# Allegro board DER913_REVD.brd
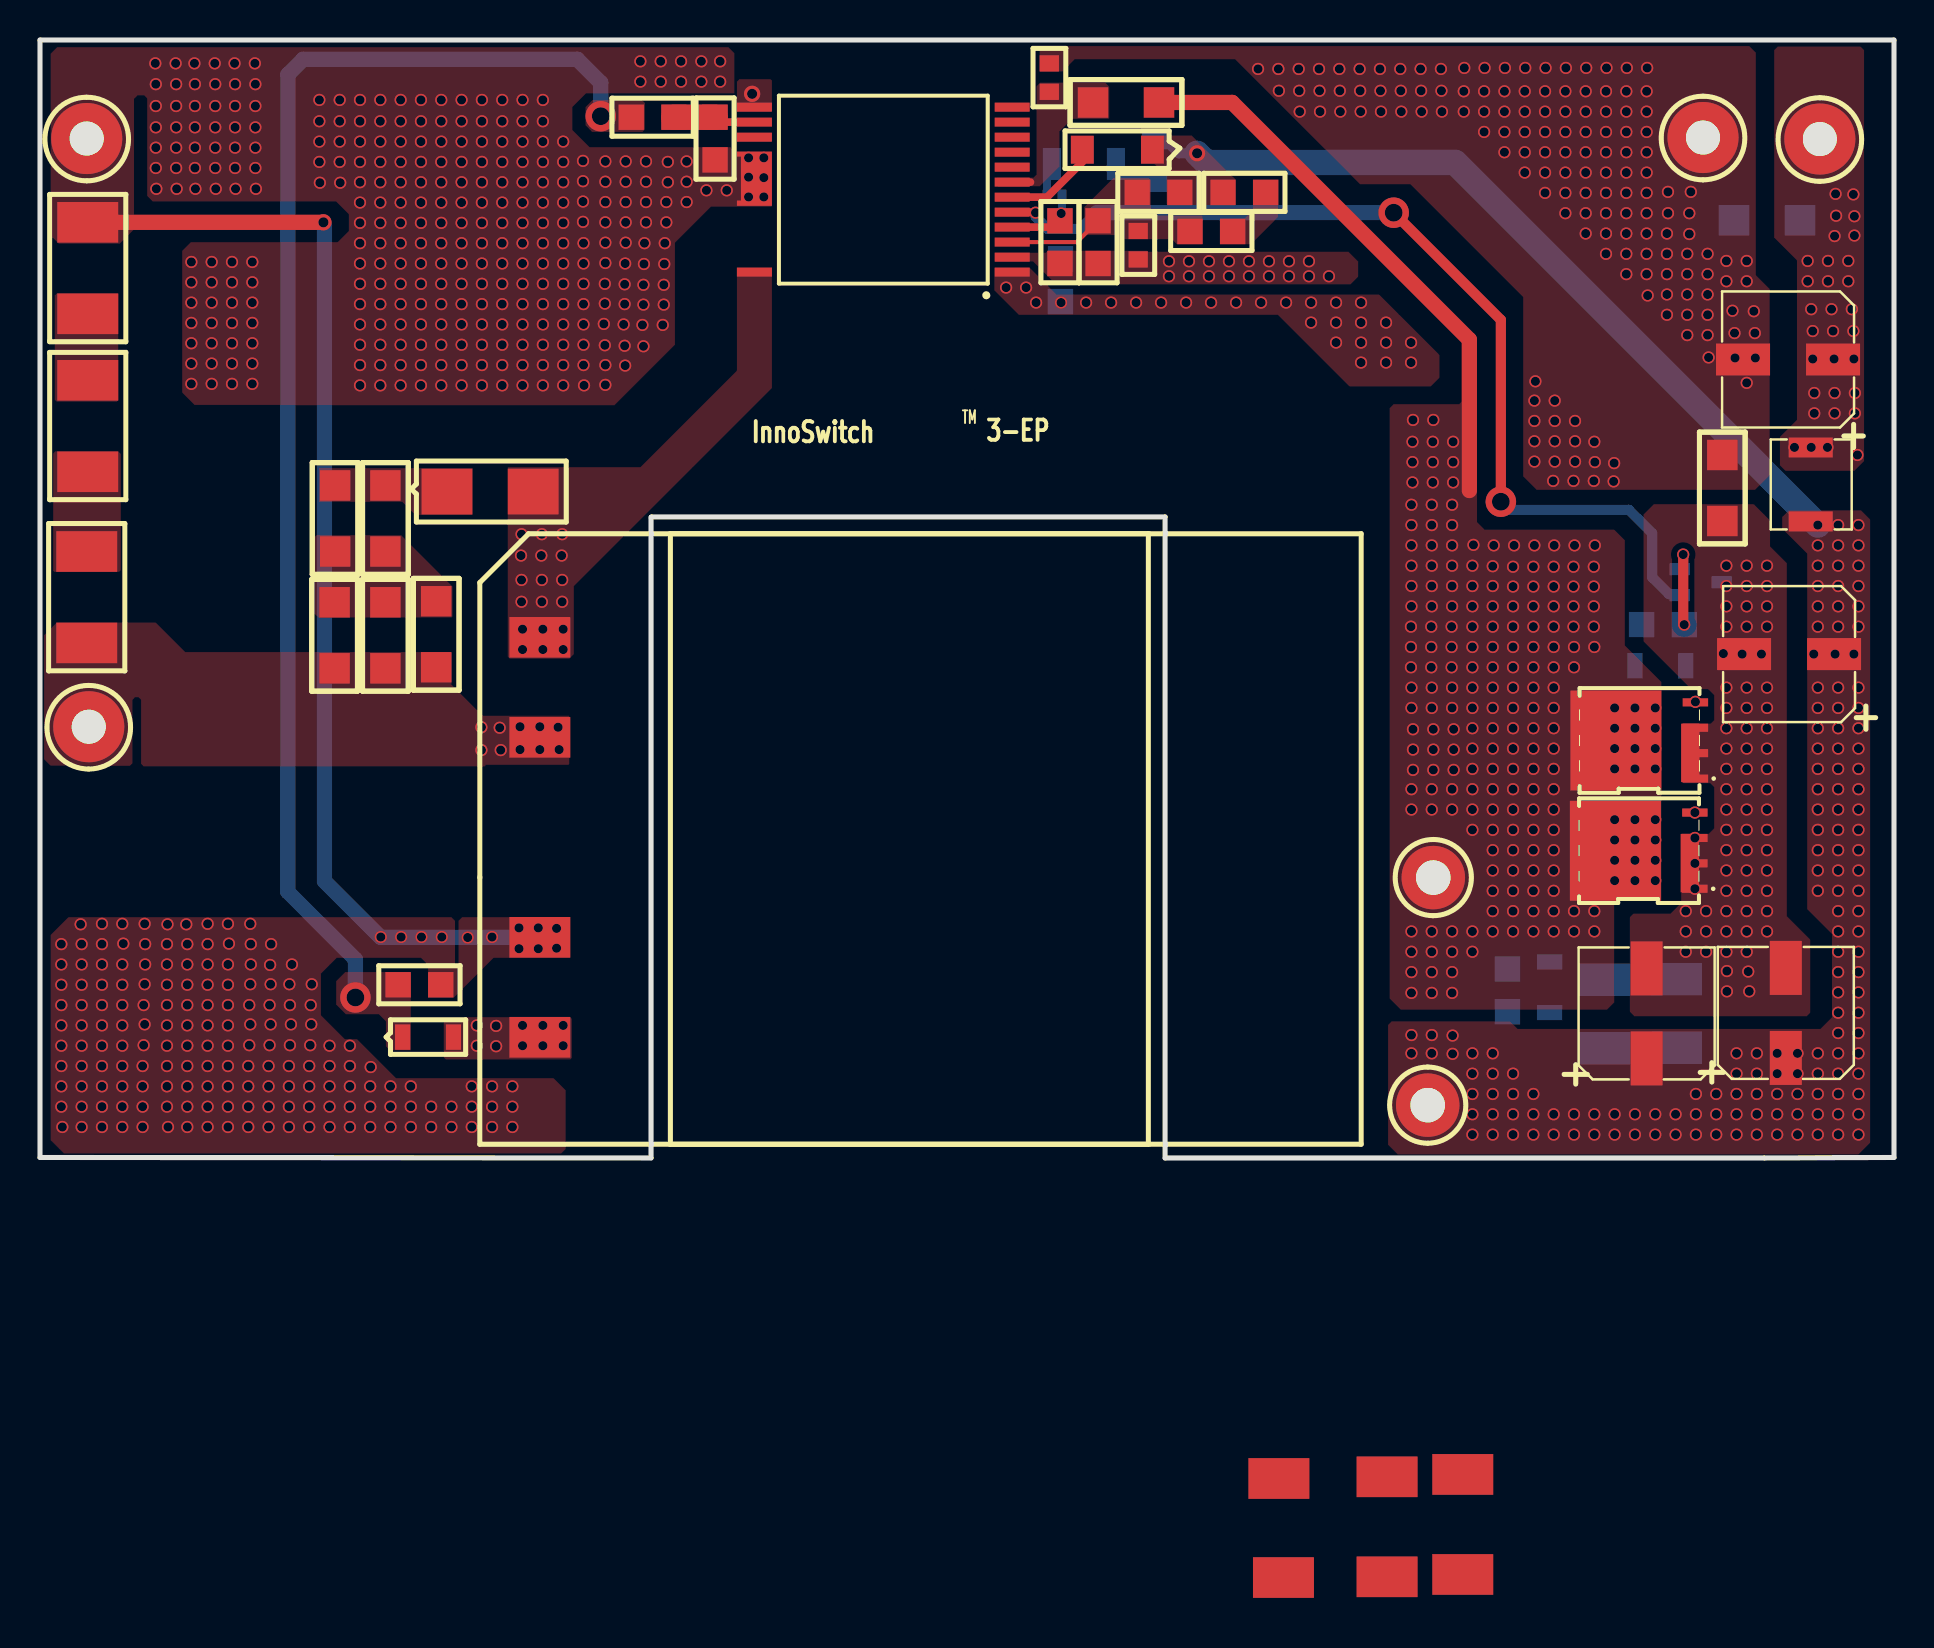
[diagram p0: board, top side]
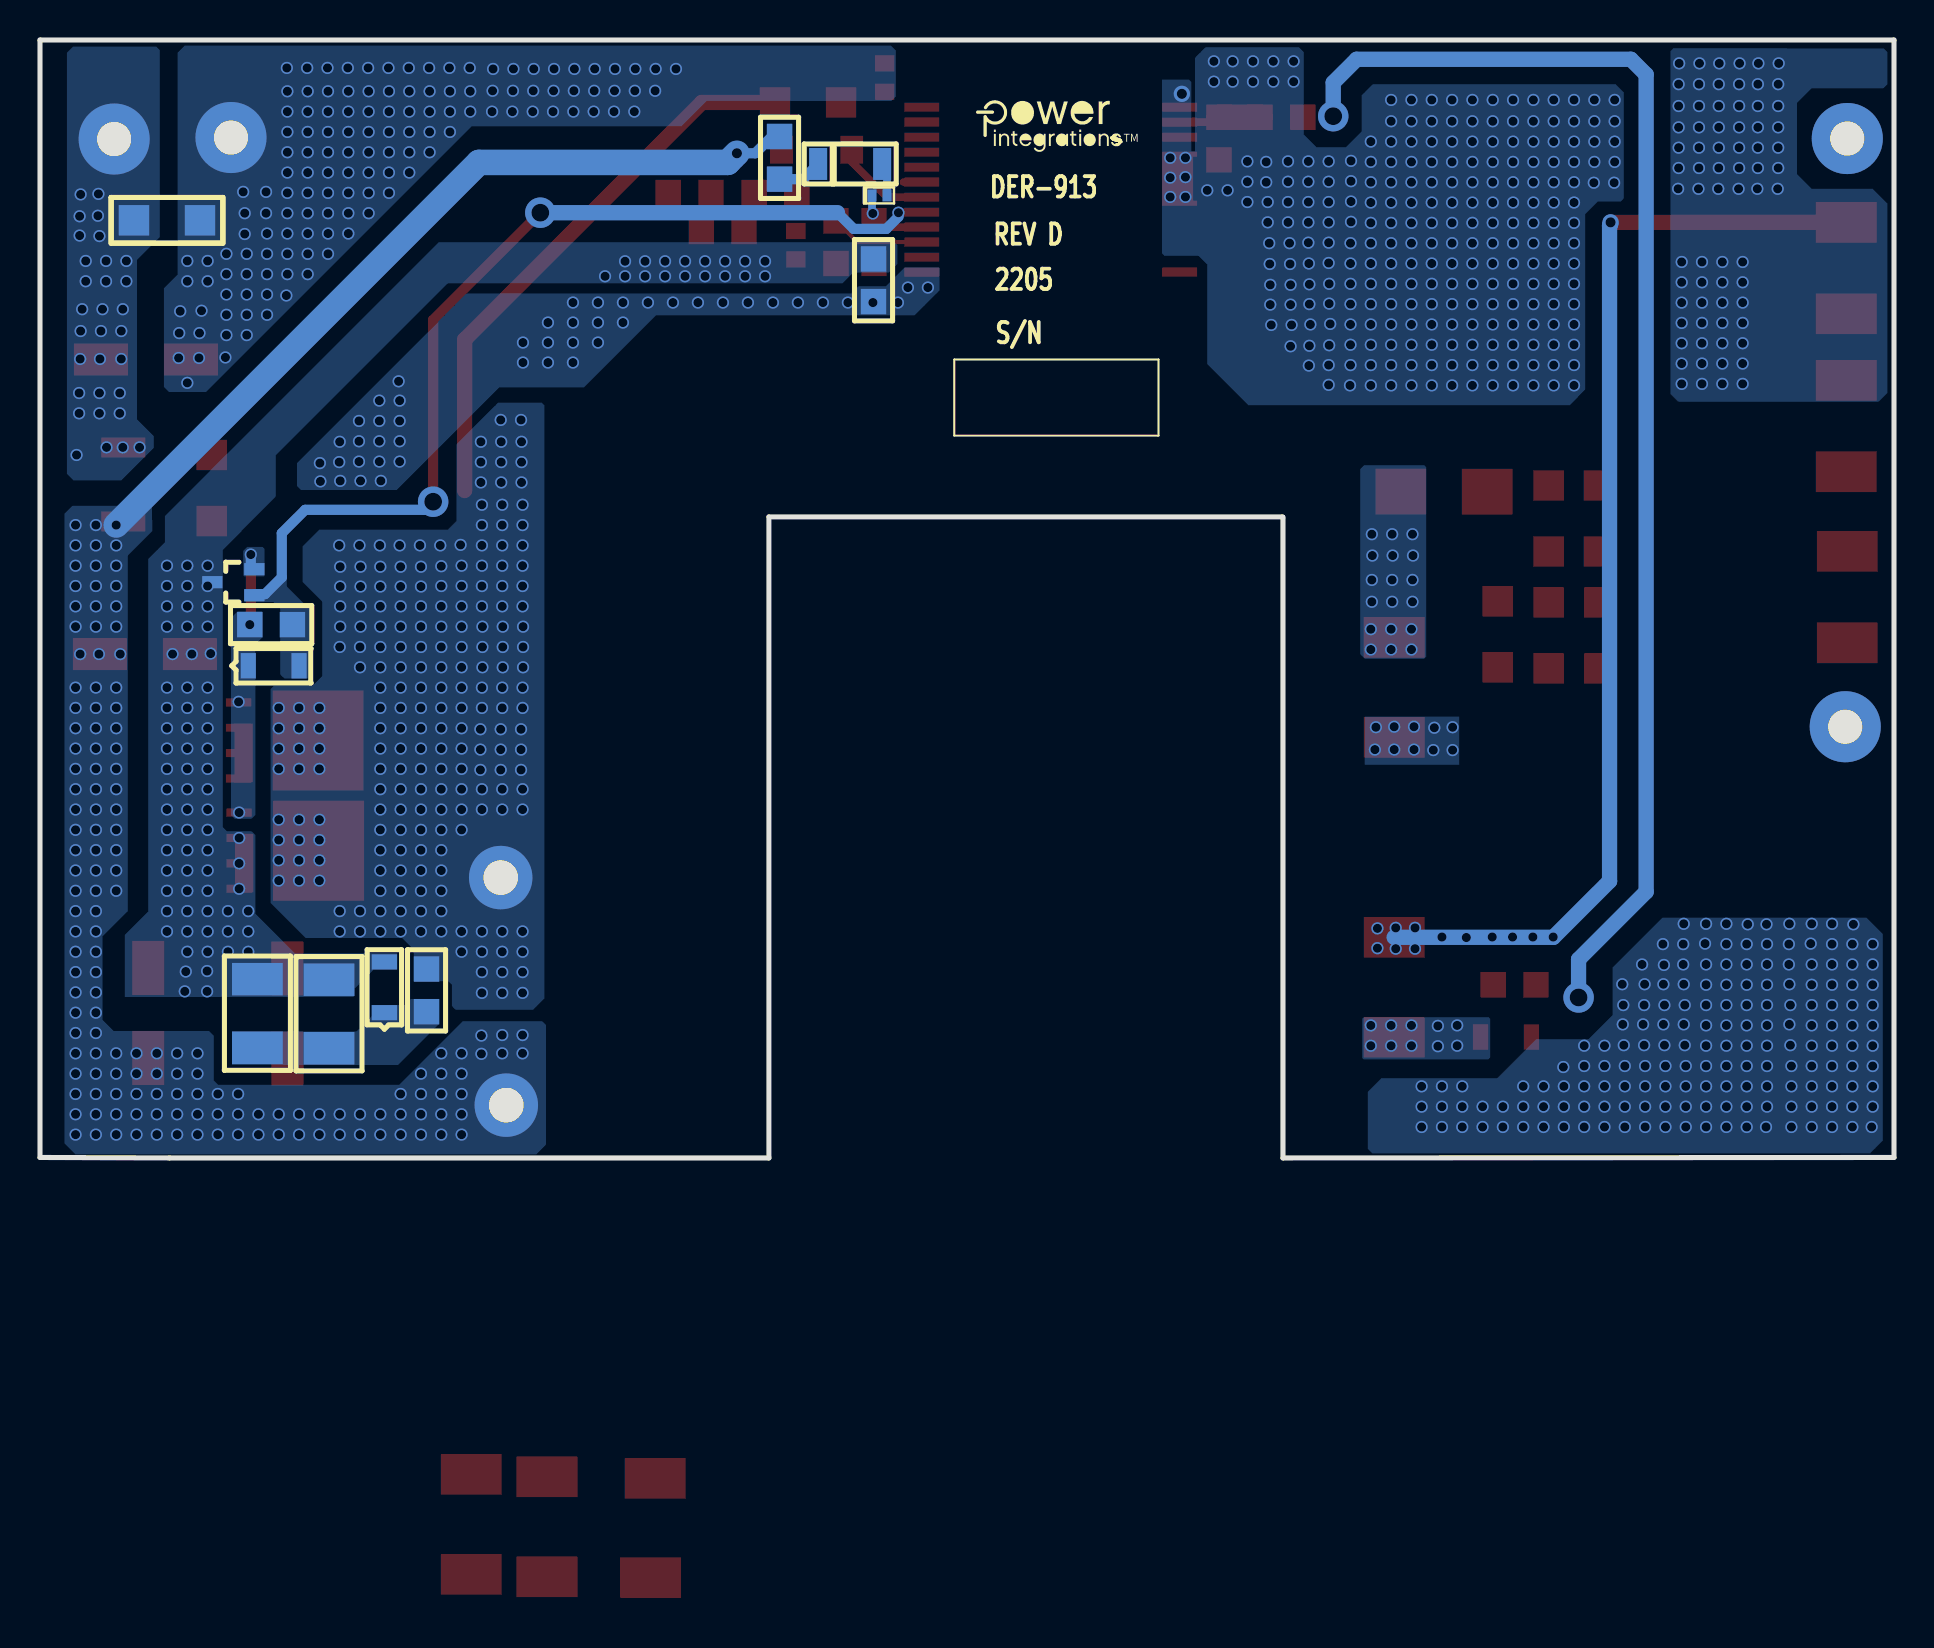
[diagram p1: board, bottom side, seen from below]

Outline 92.71 x 55.91 mm; copper layers: TOP, INNER1, INNER2, BOTTOM. Coordinates in mm from the lower left corner of the outline.
Outline path: 0,55.91 92.71,55.91 92.71,0.03 86.23,0 56.26,0 56.26,32.05 30.58,32.05 30.56,32.03 30.56,0 0,0.03 0,55.91

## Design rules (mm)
constraint set DEFAULT: min track width 0.508

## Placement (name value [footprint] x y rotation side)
C1A  47 nF  [PISMC1812]  2.34 25.76 90 top
C1B  47 nF  [PISMC1812]  2.39 34.32 90 top
C1C  47 nF  [PISMC1812]  2.39 42.21 90 top
C2  1 nF  [PISMC1206]  19.81 24.54 90 top
C3  22 uF  [PISMC0805]  17.91 8.66 0 top
C4  0.47 uF  [PISMC0805]  33.76 52.04 270 top
C5  2.2 nF  [PISMC0805]  73.38 9.45 270 bottom
C6  2.2 uF  [PISMC0805]  51 44.73 90 top
C7  330 pF  [PISMC0603]  54.91 44.93 90 top
C8  10 nF  [PISMC0805]  59.64 46.33 180 top
C9  120 uF  [PISMCUCC_F80ALELECT]  80.34 4.98 90 top
C10  120 uF  [PISMCUCC_F80ALELECT]  87.3 5 90 top
C11  120 uF  [PISMCUCC_F80ALELECT]  89.71 25.2 180 top
C13  120 uF  [PISMCUCC_F80ALELECT]  89.66 39.93 180 top
C14  2.2 uF  [PISMC1206]  88.01 46.89 180 bottom
C16  330 pF  [PISMC0603]  50.47 53.31 90 top
C17  10 nF  [PISMC0805]  51.03 44.96 270 bottom
D1  ACGRAS1W-HF  [PISMDO214AC12]  20.35 33.32 0 top
D2  NSVBAS21AHT1G  [PISMSOD323]  18.14 6.05 0 top
D3  SD103CWS-E3-08  [PISMSOD323]  79.76 24.61 0 bottom
D4  NSVBAS21AHT1G  [PISMSOD323]  75.49 7.26 90 bottom
D5  SBR0240LPW-7B  [PI_SM_DFN1006-2]  51.1 48.13 180 bottom
FL1  Hole_70mils  [PI_HOLE_70MIL]  69.39 2.62 0 top
FL2  Hole_70mils  [PI_HOLE_70MIL]  69.67 14 0 top
L1  SRP4020TA-1R5M  [PI_SM_2-SMD]  88.54 33.68 90 top
NOREF  -  []  -230.38 -144.4 0 top
NOREF#2  -  []  0 55.91 0 top
NOREF#3  -  []  -152.56 54.62 0 top
NOREF#4  -  []  92.71 0.03 90 top
NOREF#5  -  []  46.46 52.78 180 bottom
Q1  SQJ454EP-T1_GE3  [PISMPQFN5X6BLA]  82.78 18.97 90 top
Q2  SQJ454EP-T1_GE3  [PISMPQFN5X6BLA]  82.75 13.46 90 top
Q3  DMG1013UWQ-7  [PISMSOT323_GSD]  81.99 28.14 90 bottom
R1  1 Meg  [PISMR1206]  17.27 24.49 90 top
R2  1 Meg  [PISMR1206]  14.73 24.49 90 top
R3  82  [PISMR1206]  14.76 30.33 90 top
R4  82  [PISMR1206]  17.27 30.33 90 top
R5  7.68 k  [PISMR0805]  29.57 52.04 0 top
R6  100  [PISMR1206]  55.96 52.78 180 top
R7  20  [PISMR1210]  78.26 5.49 90 bottom
R8  20  [PISMR1210]  81.84 5.51 90 bottom
R9  5.49 k  [PISMR0805]  52.91 46.86 270 top
R10  100 k  [PISMR0805]  57 48.29 180 top
R11  15 k  [PISMR0805]  59.16 48.29 0 top
R12  0.015  [PISMR1206]  84.12 31.85 90 top
R13  4.7  [PISMR0805]  82.22 26.67 180 bottom
R14  4.7  [PISMR0805]  55.73 51.08 270 bottom
RTN  BLK  [PITPKEYSTONE125X125]  83.16 51.03 0 top
T1  EIQ30  [PIBOBBINEQI3010PSMTSLIMCORE]  24.99 26.04 90 top
U1  INN3647C  [PI_IC_INSOP_24D]  48.62 44.3 180 top
VIN+  RED  [PITPKEYSTONE125X125]  2.44 21.56 0 top
VIN-  BLK  [PITPKEYSTONE125X125]  2.34 50.98 0 top
VO  RED  [PITPKEYSTONE125X125]  89 50.95 0 top
VR1  SZMMSZ4683T1G  [PI_SM_SOD-123_12]  55.63 50.42 180 top
VR2  TZMB22-GS08  [PI_SM_SOD80C]  53.8 49.71 180 bottom

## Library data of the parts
C1A C1B C1C C2-C6 C8 C14 C16 C17 = CAP NP
C7 = CAP NP: alternate symbols: (pismc0603_1)
C9-C11 C13 = CAP POL
D1 D5 = DIODE
D2 D4 = DIODE: alternate symbols: (pismsod323_1)
D3 = DIODE SCHOTTKY: alternate symbols: (pismsod323_1)
FL1 FL2 = FlyingLead
L1 = INDUCTOR
Q1 Q2 = FET_N_SGD_123_4_5678: alternate symbols: (pismpqfn5x6bl)
Q3 = FET_P_GSD
R1-R14 = R
RTN VIN+ VIN- VO = TESTPOINT
T1 = BEQI30_10P_SMT/GENERIC_7
U1 = Inno3AQ_P15_3
VR1 VR2 = DIODE_ZENER

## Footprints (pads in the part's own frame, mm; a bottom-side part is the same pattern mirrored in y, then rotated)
PI_HOLE_70MIL
  round 3.175 hole 1.727: 1(0,0.025)
PI_IC_INSOP_24D
  rect 1.75x0.45 smd: 1(0,0) 2(0,-0.749) 3(0,-1.501) 4(0,-2.25) 5(0,-3) 6(0,-3.749) 7(0,-4.501) 8(0,-5.25) 9(0,-6) 10(0,-6.749) 11(0,-7.501) 12(0,-8.25) 13(12.89,-8.25) 14(12.89,-7.501) 15(12.89,-6.749) 24(12.89,0)
  custom 0.437x0.437 smd: 16(12.89,-4.671)
PI_SM_2-SMD
  rect 1.001x2.2 smd: 1(-1.849,0) 2(1.849,0)
PI_SM_DFN1006-2
  rect 0.45x0.6 smd: 1(0,0) 2(0.75,0)
PI_SM_SOD80C
  rect 0.9x1.6 smd: 1(0,0) 2(3.2,0)
PI_SM_SOD-123_12
  rect 1.143x1.397 smd: 1(0,0) 2(3.505,0)
PIBOBBINEQI3010PSMTSLIMCORE
  rect 2.032x3.048 smd: 1(0,0) 2(-5.001,0) 3(-42.062,-36.957) 4(-15.001,0) 5(-20,0) 6(-47.015,-37.186) 7(-46.98,-42.367) 8(-41.979,-42.367) 9(-46.86,-46.152) 10(-41.859,-46.152)
PISMC0603
  rect 0.813x0.965 smd: 1(0,0) 2(1.422,0)
PISMC0805
  rect 1.27x1.27 smd: 1(0,0) 2(2.134,0)
PISMC1206
  rect 1.524x1.524 smd: 1(0,0) 2(3.302,0)
PISMC1812
  rect 2.032x3.048 smd: 1(0,0) 2(4.572,0)
PISMCUCC_F80ALELECT
  rect 2.7x1.6 smd: 1(0,0) 2(4.501,0)
PISMDO214AC12
  rect 2.54x2.286 smd: 1(0,0) 2(4.318,0)
PISMPQFN5X6BLA
  rect 0.406x1.27 smd: 1(0,0) 2(1.27,0) 3(2.54,0) 4(3.81,0)
  rect 0.406x1.219 smd: 5(3.81,5.588) 6(2.54,5.588) 7(1.27,5.588) 8(0,5.588)
PISMR0805
  rect 1.27x1.27 smd: 1(0,0) 2(2.134,0)
PISMR1206
  rect 1.524x1.524 smd: 1(0,0) 2(3.302,0)
PISMR1210
  rect 1.626x2.54 smd: 1(0,0) 2(3.429,0)
PISMSOD323
  rect 0.762x1.27 smd: 1(0,0) 2(2.54,0)
PISMSOT323_GSD
  rect 0.61x1.016 smd: 1(0,0) 2(0.65,2.101) 3(1.301,0)
PITPKEYSTONE125X125
  round 3.556 hole 1.702: 1(0,0)

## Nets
GND: C1C.2 C3.2 C4.2 T1.4 U1.13(VPIN) U1.16 VIN-.1
GND SIGNAL: C13.2 C14.2 C16.2 C17.2 R12.2 RTN.1 U1.1
NC8: U1.8
NC9: U1.9
NC10: U1.10
NC11: U1.11
NC12: U1.12
NC15: U1.15
VO: C9.1 C10.1 C11.1 FL1.1 L1.1 R10.1 R11.1 R14.1 VR1.1
N37213: C1A.1 C2.1 R1.1 R2.1 T1.2 VIN+.1
N37461: C5.2 D4.1 R7.1 R8.1
N37469: C6.1 C7.1 C9.2 C10.2 C11.2 C17.1 D4.2 Q1.1 Q1.2 Q1.3(S3) Q2.1 Q2.2 Q2.3(S3) Q3.2(S) R7.2 R8.2 R9.2 R12.1 U1.2
N37817: C1A.2 C1B.1
N38055: C3.1 D2.1 R5.1
N38189: C4.1 R5.2 U1.14
N51802: C13.1 C14.1 L1.2 VO.1
N100534: C2.2 R1.2 R2.2 R3.1 R4.1
N100538: D1.1 R3.2 R4.2
N104424: C5.1 FL2.1 Q1.5 Q1.6 Q1.7 Q1.8 Q2.5 Q2.6 Q2.7 Q2.8 R6.1
N108749: C7.2 C8.2 R9.1 R10.2 U1.3
N109628: U1.6 VR1.2
N109833: C8.1 R11.2
N12285951: D3.2(CATHODE) Q1.4 Q2.4 Q3.3 R13.1
N12285992: D3.1 Q3.1 R13.2 U1.5
N12290249: D2.2 T1.5
N12293127: C16.1 R6.2 U1.7
N12298344: D1.2 T1.1 U1.24
N12325575: C6.2 D5.1 U1.4
N12326103: D5.2 VR2.2
N12333480: C1B.2 C1C.1
N12335935: R14.2 VR2.1

Pads without a net: T1 3 6 7 8 9 10

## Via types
v1: diameter 0.61, hole 0.457, TOP to BOTTOM, 1195 vias
v2: diameter 1.524, hole 0.889, TOP to BOTTOM, 4 vias
v3: diameter 0.813, hole 0.508, TOP to BOTTOM, 3 vias

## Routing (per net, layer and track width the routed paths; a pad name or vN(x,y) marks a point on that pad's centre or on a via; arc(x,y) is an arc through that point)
GND: length 56.8
  TOP w0.508: 14.3,46.79 v3(14.17,46.79)
  TOP w0.762: v3(14.17,46.79) C1C.2
  BOTTOM w0.762: T1.4 17.03,11.03 14.22,13.84 14.22,46.63 14.17,46.69 v3(14.17,46.79)
  vias: v1(1.07,10.69) v1(1.07,9.68) v1(1.07,8.66) v1(1.07,7.65) v1(1.07,6.63) v1(1.07,5.61) v1(1.07,4.6) v1(1.07,3.58) v1(1.07,2.57) v1(1.12,1.55) v1(2.03,11.68) v1(2.08,10.69) v1(2.08,9.68) v1(2.08,8.66) v1(2.08,7.65) v1(2.08,6.63) v1(2.08,5.61) v1(2.08,4.6) v1(2.08,3.58) v1(2.08,2.57) v1(2.08,1.55) v1(3.1,11.71) v1(3.1,10.69) v1(3.1,9.68) v1(3.1,8.66) v1(3.1,7.65) v1(3.1,6.63) v1(3.1,5.61) v1(3.1,4.6) v1(3.1,3.58) v1(3.1,2.57) v1(3.1,1.55) v1(4.11,11.71) v1(4.17,10.72) v1(4.11,9.68) v1(4.11,8.66) v1(4.11,7.65) v1(4.11,6.63) v1(4.11,5.61) v1(4.11,4.6) v1(4.11,3.58) v1(4.11,2.57) v1(4.11,1.55) v1(5.18,7.65) v1(5.18,5.64) v1(5.13,4.6) v1(5.13,3.58) v1(5.13,2.57) v1(5.13,1.55) v1(5.23,11.71) v1(5.26,10.69) v1(5.26,9.68) v1(5.23,8.69) v1(5.23,6.68) v1(5.77,54.74) v1(5.79,53.7) v1(5.79,52.6) v1(5.79,51.54) v1(5.79,50.52) v1(5.79,49.5) v1(5.82,48.46) v1(6.38,11.68) v1(6.35,10.69) v1(6.35,9.68) v1(6.35,8.66) v1(6.35,7.65) v1(6.35,6.63) v1(6.35,5.61) v1(6.35,4.6) v1(6.35,3.58) v1(6.35,2.57) v1(6.4,1.55) v1(6.78,54.74) v1(6.81,53.7) v1(6.81,52.6) v1(6.81,51.54) v1(6.81,50.52) v1(6.81,49.5) v1(6.83,48.46) v1(7.32,11.68) v1(7.37,10.69) v1(7.37,9.68) v1(7.37,8.66) v1(7.37,7.65) v1(7.37,6.63) v1(7.37,5.61) v1(7.37,4.6) v1(7.37,3.58) v1(7.37,2.57) v1(7.37,1.55) v1(7.57,44.81) v1(7.57,43.79) v1(7.57,42.77) v1(7.57,41.76) v1(7.57,40.74) v1(7.57,39.73) v1(7.57,38.71) v1(7.72,54.74) v1(7.75,53.7) v1(7.75,52.6) v1(7.75,51.54) v1(7.75,50.52) v1(7.75,49.5) v1(7.77,48.46) v1(8.38,11.71) v1(8.38,10.69) v1(8.38,9.68) v1(8.38,8.66) v1(8.38,7.65) v1(8.38,6.63) v1(8.38,5.61) v1(8.38,4.6) v1(8.38,3.58) v1(8.38,2.57) v1(8.38,1.55) v1(8.59,44.81) v1(8.59,43.79) v1(8.59,42.77) v1(8.59,41.76) v1(8.59,40.74) v1(8.59,39.73) v1(8.59,38.71) v1(8.74,54.74) v1(8.76,53.7) v1(8.76,52.6) v1(8.76,51.54) v1(8.76,50.52) v1(8.76,49.5) v1(8.79,48.46) v1(9.4,11.71) v1(9.4,9.68) v1(9.4,8.66) v1(9.4,7.65) v1(9.4,6.63) v1(9.4,5.61) v1(9.4,4.6) v1(9.4,3.58) v1(9.4,2.57) v1(9.4,1.55) v1(9.45,10.72) v1(9.6,44.81) v1(9.6,43.79) v1(9.6,42.77) v1(9.6,41.76) v1(9.6,40.74) v1(9.6,39.73) v1(9.6,38.71) v1(9.73,54.74) v1(9.75,53.7) v1(9.75,52.6) v1(9.75,51.54) v1(9.75,50.52) v1(9.75,49.5) v1(9.78,48.46) v1(10.46,7.65) v1(10.46,5.64) v1(10.41,4.6) v1(10.41,3.58) v1(10.41,2.57) v1(10.41,1.55) v1(10.52,11.71) v1(10.54,10.69) v1(10.54,9.68) v1(10.52,8.69) v1(10.52,6.68) v1(10.62,44.81) v1(10.62,43.79) v1(10.62,42.77) v1(10.62,41.76) v1(10.62,40.74) v1(10.62,39.73) v1(10.62,38.71) v1(10.74,54.74) v1(10.77,53.7) v1(10.77,52.6) v1(10.77,51.54) v1(10.77,50.52) v1(10.77,49.5) v1(10.79,48.46) v1(11.48,7.65) v1(11.48,5.64) v1(11.43,4.6) v1(11.43,3.58) v1(11.43,2.57) v1(11.43,1.55) v1(11.56,10.69) v1(11.51,9.65) v1(11.53,8.69) v1(11.53,6.68) v1(12.47,8.69) v1(12.5,7.65) v1(12.5,5.64) v1(12.45,4.6) v1(12.45,3.58) v1(12.45,2.57) v1(12.45,1.55) v1(12.6,9.68) v1(12.55,6.68) v1(13.46,4.6) v1(13.46,3.58) v1(13.46,2.57) v1(13.46,1.55) v1(13.59,8.69) v1(13.54,7.65) v1(13.56,6.68) v1(13.51,5.64) v1(13.97,52.91) v1(13.97,51.84) v1(13.97,50.83) v1(13.97,49.81) v1(14,48.77) v1(14.48,5.61) v1(14.48,4.6) v1(14.48,3.58) v1(14.48,2.57) v1(14.48,1.55) v1(14.99,52.91) v1(14.99,51.84) v1(14.99,50.83) v1(14.99,49.81) v1(15.01,48.77) v1(15.49,5.61) v1(15.49,4.6) v1(15.49,3.58) v1(15.49,2.57) v1(15.49,1.55) v1(16,52.91) v1(16,51.84) v1(16,50.83) v1(16,49.81) v1(16,48.79) v1(16,47.78) v1(16,46.76) v1(16,45.75) v1(16,44.73) v1(16,43.71) v1(16,42.7) v1(16,41.68) v1(16,40.67) v1(16,39.65) v1(16,38.63) v1(16.54,4.55) v1(16.51,3.58) v1(16.51,2.57) v1(16.51,1.55) v1(17.02,52.91) v1(17.02,51.84) v1(17.02,50.83) v1(17.02,49.81) v1(17.02,48.79) v1(17.02,47.78) v1(17.02,46.76) v1(17.02,45.75) v1(17.02,44.73) v1(17.02,43.71) v1(17.02,42.7) v1(17.02,41.68) v1(17.02,40.67) v1(17.02,39.65) v1(17.02,38.63) v1(17.04,11.05) v1(17.53,3.58) v1(17.53,2.57) v1(17.53,1.55) v1(18.03,52.91) v1(18.03,51.84) v1(18.03,50.83) v1(18.03,49.81) v1(18.03,48.79) v1(18.03,47.78) v1(18.03,46.76) v1(18.03,45.75) v1(18.03,44.73) v1(18.03,43.71) v1(18.03,42.7) v1(18.03,41.68) v1(18.03,40.67) v1(18.03,39.65) v1(18.03,38.63) v1(18.06,11.05) v1(18.54,3.58) v1(18.54,2.57) v1(18.54,1.55) v1(19.05,52.91) v1(19.05,51.84) v1(19.05,50.83) v1(19.05,49.81) v1(19.05,48.79) v1(19.05,47.78) v1(19.05,46.76) v1(19.05,45.75) v1(19.05,44.73) v1(19.05,43.71) v1(19.05,42.7) v1(19.05,41.68) v1(19.05,40.67) v1(19.05,39.65) v1(19.05,38.63) v1(19.08,11.05) v1(19.56,2.57) v1(19.56,1.55) v1(20.07,52.91) v1(20.07,51.84) v1(20.07,50.83) v1(20.07,49.81) v1(20.07,48.79) v1(20.07,47.78) v1(20.07,46.76) v1(20.07,45.75) v1(20.07,44.73) v1(20.07,43.71) v1(20.07,42.7) v1(20.07,41.68) v1(20.07,40.67) v1(20.07,39.65) v1(20.07,38.63) v1(20.09,11.05) v1(20.57,2.57) v1(20.57,1.55) v1(21.08,52.91) v1(21.08,51.84) v1(21.08,50.83) v1(21.08,49.81) v1(21.08,48.79) v1(21.08,47.78) v1(21.08,46.76) v1(21.08,45.75) v1(21.08,44.73) v1(21.08,43.71) v1(21.08,42.7) v1(21.08,41.68) v1(21.08,40.67) v1(21.08,39.65) v1(21.08,38.63) v1(21.39,11.02) v1(21.59,3.58) v1(21.59,2.57) v1(21.59,1.55) v1(22.1,52.91) v1(22.1,51.84) v1(22.1,50.83) v1(22.1,49.81) v1(22.1,48.79) v1(22.1,47.78) v1(22.1,46.76) v1(22.1,45.75) v1(22.1,44.73) v1(22.1,43.71) v1(22.1,42.7) v1(22.1,41.68) v1(22.1,40.67) v1(22.1,39.65) v1(22.1,38.63) v1(22.61,11.05) v1(22.61,3.58) v1(22.61,2.57) v1(22.61,1.55) v1(23.11,52.91) v1(23.11,51.84) v1(23.11,50.83) v1(23.11,49.81) v1(23.11,48.79) v1(23.11,47.78) v1(23.11,46.76) v1(23.11,45.75) v1(23.11,44.73) v1(23.11,43.71) v1(23.11,42.7) v1(23.11,41.68) v1(23.11,40.67) v1(23.11,39.65) v1(23.11,38.63) v1(23.62,3.58) v1(23.62,2.57) v1(23.62,1.55) v1(23.95,11.51) v1(23.95,10.46) v1(24.13,52.91) v1(24.13,51.84) v1(24.13,50.83) v1(24.13,49.81) v1(24.13,48.79) v1(24.13,47.78) v1(24.13,46.76) v1(24.13,45.75) v1(24.13,44.73) v1(24.13,43.71) v1(24.13,42.7) v1(24.13,41.68) v1(24.13,40.67) v1(24.13,39.65) v1(24.13,38.63) v1(24.92,11.51) v1(24.92,10.46) v1(25.15,52.91) v1(25.15,51.84) v1(25.15,50.83) v1(25.15,49.81) v1(25.15,48.79) v1(25.15,47.78) v1(25.15,46.76) v1(25.15,45.75) v1(25.15,44.73) v1(25.15,43.71) v1(25.15,42.7) v1(25.15,41.68) v1(25.15,40.67) v1(25.15,39.65) v1(25.15,38.63) v1(25.83,11.48) v1(25.83,10.49) v1(26.16,50.83) v1(26.16,49.81) v1(26.16,48.79) v1(26.16,47.78) v1(26.16,46.76) v1(26.16,45.75) v1(26.16,44.73) v1(26.16,43.71) v1(26.16,42.7) v1(26.16,41.68) v1(26.16,40.67) v1(26.16,39.65) v1(26.16,38.63) v1(27.15,49.86) v1(27.15,48.84) v1(27.15,47.83) v1(27.15,46.81) v1(27.18,45.75) v1(27.18,44.73) v1(27.18,43.71) v1(27.18,42.7) v1(27.18,41.68) v1(27.18,40.67) v1(27.18,39.65) v1(27.2,38.63) v1(28.19,41.71) v1(28.27,49.83) v1(28.27,48.82) v1(28.27,47.8) v1(28.27,46.79) v1(28.27,45.77) v1(28.27,44.75) v1(28.24,43.71) v1(28.24,42.72) v1(28.24,40.64) v1(28.27,39.65) v1(28.27,38.66) v1(29.18,41.68) v1(29.29,49.83) v1(29.29,48.82) v1(29.29,47.8) v1(29.29,46.79) v1(29.29,45.77) v1(29.26,44.73) v1(29.24,43.69) v1(29.24,42.7) v1(29.24,40.61) v1(29.26,39.62) v1(30.02,54.84) v1(30.02,53.82) v1(30.2,44.7) v1(30.18,43.66) v1(30.18,42.67) v1(30.12,41.66) v1(30.18,40.59) v1(30.23,45.75) v1(30.3,49.83) v1(30.3,48.82) v1(30.3,47.8) v1(30.3,46.79) v1(31.04,54.84) v1(31.04,53.82) v1(31.19,43.66) v1(31.19,42.67) v1(31.14,41.66) v1(31.24,45.75) v1(31.22,44.7) v1(31.39,49.81) v1(31.39,48.79) v1(31.32,47.8) v1(31.32,46.79) v1(32.05,54.84) v1(32.05,53.82) v1(32.33,49.83) v1(32.33,48.82) v1(32.33,47.8) v1(33.07,54.84) v1(33.07,53.82) v1(33.32,48.39) v1(34.01,54.84) v1(34.01,53.82) v1(34.34,48.39) v1(35.43,50.01) v1(35.43,49.05) v1(35.43,48.06) v1(36.2,50.01) v1(36.2,49.02) v1(36.2,48.06) v3(35.61,53.21)
GND SIGNAL:
  vias: v1(48.31,43.53) v1(49.31,43.53) v1(49.81,42.78) v1(51.06,42.78) v1(52.31,42.78) v1(53.56,42.78) v1(54.81,42.78) v1(56.06,42.78) v1(57.31,42.78) v1(58.56,42.78) v1(59.81,42.78) v1(60.91,54.46) v1(61.06,42.78) v1(61.93,54.46) v1(61.95,53.37) v1(62.31,42.78) v1(62.94,54.46) v1(62.97,53.37) v1(62.99,52.32) v1(63.56,42.78) v1(63.56,41.78) v1(63.96,54.46) v1(63.98,53.37) v1(64.01,52.32) v1(64.81,42.78) v1(64.81,41.78) v1(64.81,40.78) v1(64.97,54.46) v1(65,53.37) v1(65.02,52.32) v1(65.99,54.46) v1(66.01,53.37) v1(66.04,52.32) v1(66.06,42.78) v1(66.06,41.78) v1(66.06,40.78) v1(66.06,39.78) v1(67.01,54.46) v1(67.03,53.37) v1(67.06,52.32) v1(67.31,41.78) v1(67.31,40.78) v1(67.31,39.78) v1(68.02,54.46) v1(68.05,53.37) v1(68.07,52.32) v1(68.56,40.78) v1(68.56,39.78) v1(69.04,54.46) v1(69.06,53.37) v1(69.09,52.32) v1(70.05,54.46) v1(70.08,53.37) v1(70.1,52.32) v1(71.2,53.34) v1(71.2,52.32) v1(71.22,54.51) v1(72.24,54.51) v1(72.21,53.34) v1(72.21,52.32) v1(72.21,51.31) v1(73.25,54.51) v1(73.23,53.34) v1(73.23,52.32) v1(73.23,51.31) v1(73.23,50.29) v1(74.27,54.51) v1(74.24,53.34) v1(74.24,52.32) v1(74.24,51.31) v1(74.24,50.29) v1(74.24,49.28) v1(74.78,38.84) v1(74.73,37.87) v1(74.73,36.86) v1(74.73,35.84) v1(74.73,34.82) v1(75.29,54.51) v1(75.26,53.34) v1(75.26,52.32) v1(75.26,51.31) v1(75.26,50.29) v1(75.26,49.28) v1(75.26,48.26) v1(75.67,33.86) v1(75.74,37.87) v1(75.74,36.86) v1(75.74,35.84) v1(75.74,34.82) v1(76.28,53.34) v1(76.28,52.32) v1(76.28,51.31) v1(76.28,50.29) v1(76.28,49.28) v1(76.28,48.26) v1(76.28,47.24) v1(76.3,54.51) v1(76.68,33.86) v1(76.76,36.86) v1(76.76,35.84) v1(76.76,34.82) v1(77.29,53.34) v1(77.29,52.32) v1(77.29,51.31) v1(77.29,50.29) v1(77.29,49.28) v1(77.29,48.26) v1(77.29,47.24) v1(77.29,46.23) v1(77.32,54.51) v1(77.7,33.86) v1(77.72,35.81) v1(77.75,34.8) v1(78.33,54.51) v1(78.31,53.34) v1(78.31,52.32) v1(78.31,51.31) v1(78.31,50.29) v1(78.31,49.28) v1(78.31,48.26) v1(78.31,47.24) v1(78.31,46.23) v1(78.31,45.21) v1(78.69,33.83) v1(78.71,34.75) v1(79.35,54.51) v1(79.32,53.34) v1(79.32,52.32) v1(79.32,51.31) v1(79.32,50.29) v1(79.32,49.28) v1(79.32,48.26) v1(79.32,47.24) v1(79.32,46.23) v1(79.32,45.21) v1(79.32,44.2) v1(80.37,54.51) v1(80.34,53.34) v1(80.34,52.32) v1(80.34,51.31) v1(80.34,50.29) v1(80.34,49.28) v1(80.34,48.26) v1(80.34,47.24) v1(80.34,46.23) v1(80.34,45.21) v1(80.34,44.2) v1(80.39,43.13) v1(81.36,46.23) v1(81.36,45.21) v1(81.36,44.2) v1(81.36,43.18) v1(81.36,42.16) v1(81.41,48.31) v1(81.41,47.24) v1(82.37,45.21) v1(82.37,44.2) v1(82.37,43.18) v1(82.37,42.16) v1(82.37,41.15) v1(82.47,47.24) v1(82.47,46.2) v1(82.55,48.31) v1(83.39,45.21) v1(83.39,44.2) v1(83.39,43.18) v1(83.39,42.16) v1(83.39,41.15) v1(83.44,40.03) v1(84.33,44.86) v1(84.33,43.84) v1(84.63,42.37) v1(84.73,41.25) v1(84.76,40.01) v1(85.34,44.86) v1(85.34,43.84) v1(85.34,38.76) v1(85.7,42.34) v1(85.75,41.25) v1(85.78,40.01)
VO: length 41.2
  BOTTOM w0.508: R14.1 56.11,51.08 56.95,50.24 v3(57.86,50.24)
  BOTTOM w1.27: v1(88.9,31.65) 70.76,49.78 58.32,49.78 v3(57.86,50.24)
  vias: v1(68.58,6.15) v1(68.58,5.23) v1(69.6,6.15) v1(69.6,5.23) v1(70.64,6.12) v1(70.64,5.21) v1(71.63,5.23) v1(71.63,4.22) v1(71.63,3.2) v1(71.63,2.18) v1(71.63,1.17) v1(72.64,5.23) v1(72.64,4.22) v1(72.64,3.2) v1(72.64,2.18) v1(72.64,1.17) v1(73.66,4.22) v1(73.66,3.2) v1(73.66,2.18) v1(73.66,1.17) v1(74.68,3.2) v1(74.68,2.18) v1(74.68,1.17) v1(75.69,2.18) v1(75.69,1.17) v1(76.71,2.18) v1(76.71,1.17) v1(77.72,2.18) v1(77.72,1.17) v1(78.74,2.18) v1(78.74,1.17) v1(79.76,2.18) v1(79.76,1.17) v1(80.77,2.18) v1(80.77,1.17) v1(81.79,2.18) v1(81.79,1.17) v1(82.8,3.2) v1(82.8,2.18) v1(82.8,1.17) v1(83.82,3.2) v1(83.82,2.18) v1(83.82,1.17) v1(84.84,5.23) v1(84.84,4.22) v1(84.84,3.2) v1(84.84,2.18) v1(84.84,1.17) v1(85.85,5.23) v1(85.85,4.22) v1(85.85,3.2) v1(85.85,2.18) v1(85.85,1.17) v1(86.87,5.23) v1(86.87,4.22) v1(86.87,3.2) v1(86.87,2.18) v1(86.87,1.17) v1(87.88,5.23) v1(87.88,4.22) v1(87.88,3.2) v1(87.88,2.18) v1(87.88,1.17) v1(88.7,25.2) v1(88.9,30.63) v1(88.9,29.62) v1(88.9,28.6) v1(88.9,27.58) v1(88.9,26.57) v1(88.9,23.52) v1(88.9,22.5) v1(88.9,21.49) v1(88.9,20.47) v1(88.9,19.46) v1(88.9,18.44) v1(88.9,17.42) v1(88.9,16.41) v1(88.9,15.39) v1(88.9,14.38) v1(88.9,13.36) v1(88.9,5.23) v1(88.9,4.22) v1(88.9,3.2) v1(88.9,2.18) v1(88.9,1.17) v1(89.76,25.2) v1(89.92,31.65) v1(89.92,30.63) v1(89.92,29.62) v1(89.92,28.6) v1(89.92,27.58) v1(89.92,26.57) v1(89.92,23.52) v1(89.92,22.5) v1(89.92,21.49) v1(89.92,20.47) v1(89.92,19.46) v1(89.92,18.44) v1(89.92,17.42) v1(89.92,16.41) v1(89.92,15.39) v1(89.92,14.38) v1(89.92,13.36) v1(89.92,12.34) v1(89.92,11.33) v1(89.92,10.31) v1(89.92,9.3) v1(89.92,8.28) v1(89.92,7.26) v1(89.92,6.25) v1(89.92,5.23) v1(89.92,4.22) v1(89.92,3.2) v1(89.92,2.18) v1(89.92,1.17) v1(90.7,25.2) v1(90.93,31.65) v1(90.93,30.63) v1(90.93,29.62) v1(90.93,28.6) v1(90.93,27.58) v1(90.93,26.57) v1(90.93,23.52) v1(90.93,22.5) v1(90.93,21.49) v1(90.93,20.47) v1(90.93,19.46) v1(90.93,18.44) v1(90.93,17.42) v1(90.93,16.41) v1(90.93,15.39) v1(90.93,14.38) v1(90.93,13.36) v1(90.93,12.34) v1(90.93,11.33) v1(90.93,10.31) v1(90.93,9.3) v1(90.93,8.28) v1(90.93,7.26) v1(90.93,6.25) v1(90.93,5.23) v1(90.93,4.22) v1(90.93,3.2) v1(90.93,2.18) v1(90.93,1.17)
N37213:
  vias: v1(22.07,21.54) v1(22.07,20.4) v1(22.99,21.51) v1(23.04,20.4) v1(24,21.56) v1(24,20.42) v1(24.99,21.56) v1(24.99,20.42) v1(25.91,21.54) v1(25.96,20.42)
N37469:
  vias: v1(56.45,44.84) v1(56.45,44.09) v1(57.45,44.84) v1(57.45,44.09) v1(58.45,44.84) v1(58.45,44.09) v1(59.45,44.84) v1(59.45,44.09) v1(60.45,44.84) v1(60.45,44.09) v1(61.45,44.84) v1(61.45,44.09) v1(62.45,44.84) v1(62.45,44.09) v1(63.45,44.84) v1(63.45,44.09) v1(64.45,44.09) v1(82.3,12.34) v1(82.3,11.33) v1(82.3,10.31) v1(82.75,16) v1(82.75,14.73) v1(82.75,13.46) v1(83.31,12.34) v1(83.31,11.33) v1(83.31,10.31) v1(84.18,25.22) v1(84.33,29.62) v1(84.33,28.6) v1(84.33,27.58) v1(84.33,26.57) v1(84.33,23.52) v1(84.33,22.5) v1(84.33,21.49) v1(84.33,20.47) v1(84.33,19.46) v1(84.33,18.44) v1(84.33,17.42) v1(84.33,16.41) v1(84.33,15.39) v1(84.33,14.38) v1(84.33,13.36) v1(84.33,12.34) v1(84.33,11.33) v1(84.33,10.31) v1(84.35,9.35) v1(84.35,8.33) v1(85.12,25.2) v1(85.34,29.62) v1(85.34,28.6) v1(85.34,27.58) v1(85.34,26.57) v1(85.34,23.52) v1(85.34,22.5) v1(85.34,21.49) v1(85.34,20.47) v1(85.34,19.46) v1(85.34,18.44) v1(85.34,17.42) v1(85.34,16.41) v1(85.34,15.39) v1(85.34,14.38) v1(85.34,13.36) v1(85.34,12.34) v1(85.34,11.33) v1(85.34,10.31) v1(85.42,9.32) v1(85.47,8.33) v1(86.08,25.2) v1(86.36,29.62) v1(86.36,28.6) v1(86.36,27.58) v1(86.36,26.57) v1(86.36,23.52) v1(86.36,22.5) v1(86.36,21.49) v1(86.36,20.47) v1(86.36,19.46) v1(86.36,18.44) v1(86.36,17.42) v1(86.36,16.41) v1(86.36,15.39) v1(86.36,14.38) v1(86.36,13.36) v1(86.36,12.34) v1(86.36,11.33)
N38055: length 65.7
  BOTTOM w0.762: v2(15.77,8.03) 15.77,9.93 12.4,13.31 12.4,54.18 13.16,54.94 26.87,54.94 28.04,53.77 v2(28.04,52.1)
N38189: length 4.1
  TOP w0.381: C4.1 34,51.8 U1.14
  TOP w1.27: R5.2 C4.1
N51802:
  vias: v1(87.73,35.53) v1(88.39,44.86) v1(88.39,43.84) v1(88.57,42.44) v1(88.57,35.53) v1(88.65,41.35) v1(88.65,39.95) v1(88.72,38.25) v1(88.72,37.24) v1(89.38,35.53) v1(89.41,44.86) v1(89.41,43.84) v1(89.59,42.44) v1(89.66,41.35) v1(89.79,48.21) v1(89.74,46.1) v1(89.71,39.95) v1(89.74,38.25) v1(89.74,37.24) v1(89.81,47.12) v1(90.42,44.86) v1(90.42,43.84) v1(90.68,48.18) v1(90.6,42.44) v1(90.68,41.35) v1(90.73,47.09) v1(90.73,46.13) v1(90.7,39.95) v1(90.75,38.25) v1(90.75,37.24) v1(90.88,35.15)
N104424: length 28
  TOP w0.762: R6.1 59.61,52.78 71.48,40.92 71.48,33.38
  vias: v1(68.58,32.66) v1(68.58,31.65) v1(68.58,30.63) v1(68.58,29.62) v1(68.58,28.6) v1(68.58,27.58) v1(68.55,26.57) v1(68.55,25.55) v1(68.55,24.54) v1(68.58,23.52) v1(68.58,22.5) v1(68.58,18.44) v1(68.58,17.42) v1(68.58,11.33) v1(68.58,10.31) v1(68.58,9.3) v1(68.58,8.26) v1(68.66,36.91) v1(68.63,35.81) v1(68.63,34.8) v1(68.63,33.78) v1(68.66,21.44) v1(68.66,20.42) v1(68.66,19.41) v1(69.6,32.66) v1(69.6,31.65) v1(69.6,30.63) v1(69.6,29.62) v1(69.6,28.6) v1(69.6,27.58) v1(69.57,26.57) v1(69.57,25.55) v1(69.57,24.54) v1(69.6,23.52) v1(69.6,22.5) v1(69.6,18.44) v1(69.6,17.42) v1(69.6,11.33) v1(69.6,10.31) v1(69.6,9.3) v1(69.6,8.26) v1(69.67,36.91) v1(69.65,35.81) v1(69.65,34.8) v1(69.65,33.78) v1(69.67,21.44) v1(69.67,20.42) v1(69.67,19.41) v1(70.59,26.57) v1(70.59,25.55) v1(70.59,24.54) v1(70.66,35.81) v1(70.66,34.8) v1(70.66,33.78) v1(70.61,32.66) v1(70.61,31.65) v1(70.61,30.63) v1(70.61,29.62) v1(70.61,28.6) v1(70.61,27.58) v1(70.61,23.52) v1(70.61,22.5) v1(70.69,21.44) v1(70.69,20.42) v1(70.69,19.41) v1(70.61,18.44) v1(70.61,17.42) v1(70.61,11.33) v1(70.61,10.31) v1(70.61,9.3) v1(70.61,8.26) v1(71.68,30.66) v1(71.63,29.62) v1(71.63,28.6) v1(71.63,27.58) v1(71.63,26.57) v1(71.63,25.55) v1(71.63,24.54) v1(71.63,23.52) v1(71.63,22.5) v1(71.63,21.49) v1(71.63,20.47) v1(71.63,19.46) v1(71.63,18.44) v1(71.63,17.42) v1(71.63,16.41) v1(71.63,11.33) v1(71.63,10.31) v1(72.69,30.63) v1(72.64,29.59) v1(72.64,28.6) v1(72.64,27.58) v1(72.64,26.57) v1(72.64,25.55) v1(72.64,24.54) v1(72.64,23.52) v1(72.64,22.5) v1(72.64,21.49) v1(72.64,20.47) v1(72.64,19.46) v1(72.64,18.44) v1(72.64,17.42) v1(72.64,16.41) v1(72.64,15.39) v1(72.64,14.38) v1(72.64,13.36) v1(72.64,12.34) v1(72.64,11.33) v1(73.66,29.57) v1(73.66,28.57) v1(73.66,27.58) v1(73.66,26.57) v1(73.66,25.55) v1(73.66,24.54) v1(73.66,23.52) v1(73.66,22.5) v1(73.66,21.49) v1(73.66,20.47) v1(73.66,19.46) v1(73.66,18.44) v1(73.66,17.42) v1(73.66,16.41) v1(73.66,15.39) v1(73.66,14.38) v1(73.66,13.36) v1(73.66,12.34) v1(73.66,11.33) v1(73.71,30.63) v1(74.68,29.57) v1(74.68,28.57) v1(74.68,27.58) v1(74.68,26.57) v1(74.68,25.55) v1(74.68,24.54) v1(74.68,23.52) v1(74.68,22.5) v1(74.68,21.49) v1(74.68,20.47) v1(74.68,19.46) v1(74.68,18.44) v1(74.68,17.42) v1(74.68,16.41) v1(74.68,15.39) v1(74.68,14.38) v1(74.68,13.36) v1(74.68,12.34) v1(74.68,11.33) v1(74.73,30.63) v1(75.69,29.57) v1(75.69,28.57) v1(75.69,27.58) v1(75.69,26.57) v1(75.69,25.55) v1(75.69,24.54) v1(75.69,23.52) v1(75.69,22.5) v1(75.69,21.49) v1(75.69,20.47) v1(75.69,19.46) v1(75.69,18.44) v1(75.69,17.42) v1(75.69,16.41) v1(75.69,15.39) v1(75.69,14.38) v1(75.69,13.36) v1(75.69,12.34) v1(75.69,11.33) v1(75.72,30.63) v1(76.68,29.57) v1(76.68,28.57) v1(76.68,27.58) v1(76.68,26.57) v1(76.73,30.63) v1(76.71,25.55) v1(76.71,24.54) v1(76.71,12.34) v1(76.71,11.33) v1(77.7,29.57) v1(77.7,28.57) v1(77.7,27.58) v1(77.7,26.57) v1(77.75,30.63) v1(77.72,25.55) v1(77.72,12.34) v1(77.72,11.33) v1(78.74,22.5) v1(78.74,21.49) v1(78.74,20.47) v1(78.74,19.46) v1(78.74,16.92) v1(78.74,15.9) v1(78.74,14.88) v1(78.74,13.87) v1(79.76,22.5) v1(79.76,21.49) v1(79.76,20.47) v1(79.76,19.46) v1(79.76,16.92) v1(79.76,15.9) v1(79.76,14.88) v1(79.76,13.87) v1(80.77,22.5) v1(80.77,21.49) v1(80.77,20.47) v1(80.77,19.46) v1(80.77,16.92) v1(80.77,15.9) v1(80.77,14.88) v1(80.77,13.87)
N108749: length 4.7
  TOP w0.203: R9.1 51.84,45.8 U1.3
N109628: length 4.8
  TOP w0.381: U1.6 50.36,48.05 52.12,49.81 VR1.2
N12285951: length 4.5
  TOP w0.508: v1(82.17,30.18) 82.17,26.72 v1(82.22,26.67) ; Q1.4 v1(82.78,22.81)
  BOTTOM w0.508: v1(82.17,30.18) 82.17,29.62 Q3.3 ; v1(82.22,26.67) 82.3,26.59
  vias: v1(82.75,17.27)
N12285992: length 48.7
  TOP w0.381: v1(49.78,47.27) 49.76,47.3 U1.5
  TOP w0.508: v2(73.05,32.82) 73.05,41.91 v2(67.69,47.27)
  BOTTOM w0.508: Q3.1 81.94,28.19 81.46,28.19 80.62,29.03 80.62,31.24 79.45,32.41 73.46,32.41 v2(73.05,32.82) ; 52.83,47.27 52.02,46.46 50.39,46.46 49.78,47.07 v1(49.78,47.27)
  BOTTOM w0.762: 52.83,47.27 v2(67.69,47.27)
N12290249:
  vias: v1(21.84,6.63) v1(21.84,5.61) v1(22.81,6.6) v1(22.81,5.59) v1(24.13,6.63) v1(24.13,5.61) v1(25.15,6.63) v1(25.15,5.61) v1(26.16,6.63) v1(26.16,5.61)
N12293127: length 0.9
  TOP w0.381: 49.53,48.8 U1.7
N12298344:
  vias: v1(24.08,31.19) v1(24.05,30.12) v1(24.08,28.91) v1(24.08,27.81) v1(24.13,26.44) v1(24.13,25.43) v1(25.1,31.19) v1(25.07,30.12) v1(25.1,28.91) v1(25.1,27.81) v1(25.15,26.44) v1(25.15,25.43) v1(26.09,30.12) v1(26.11,31.19) v1(26.11,28.91) v1(26.11,27.81) v1(26.16,26.44) v1(26.16,25.43)
N12325575: length 3.4
  TOP w0.381: C6.2 50.69,46.55 U1.4
  BOTTOM w0.381: v1(51.07,47.23) 51.1,47.27 D5.1
N12326103: length 1.7
  BOTTOM w0.381: VR2.2 50.35,49.47 D5.2
N12335935: length 2.2
  BOTTOM w0.508: 55.73,48.95 54.56,48.95 VR2.1

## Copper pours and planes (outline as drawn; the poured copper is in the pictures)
GND on TOP: 36.6,52.32 36.6,53.87 36.53,53.95 34.98,53.95 34.85,53.82 34.85,52.35 34.87,52.32
GND on TOP: 26.06,0.23 26.29,0.46 26.29,3.38 25.68,3.99 17.81,3.99 15.85,5.94 15.24,5.94 14.05,7.14 14.05,9.22 14.83,10.01 19.05,10.01 19.41,9.65 19.41,8.03 20.7,8.03 22.68,10.01 26.34,10.01 26.37,10.03 26.37,12.01 26.34,12.04 21.11,12.04 20.93,11.86 20.93,9.55 20.75,9.55 20.75,11.86 20.57,12.04 1.42,12.04 0.53,11.15 0.53,0.89 1.19,0.23
GND on TOP: 34.42,55.55 34.72,55.25 34.72,53.24 27.3,53.24 26.62,52.55 26.62,51.41 27.48,50.55 34.52,50.55 34.75,50.32 36.6,50.32 36.6,47.6 36.58,47.57 33.55,47.57 31.75,45.77 31.75,40.67 28.73,37.64 12.12,37.64 12.1,37.66 7.73,37.66 7.11,38.28 7.11,45.36 7.54,45.8 14.88,45.8 15.44,46.36 15.44,47.19 14.81,47.83 5.64,47.83 5.36,48.11 5.36,52.98 5.21,53.14 4.88,53.14 4.7,52.96 4.7,46.43 3.99,45.72 0.94,45.72 0.53,46.13 0.53,55.22 0.86,55.55
GND on BOTTOM: 5.38,55.5 11.02,55.5 11.18,55.35 11.18,38.2 10.79,37.82 0.76,37.82 0.33,38.25 0.33,47.73 1.07,48.46 4.11,48.46 4.85,49.2 4.85,52.76 4.11,53.49 0.53,53.49 0.33,53.7 0.33,55.3 0.53,55.5 0.55,55.49 5.37,55.49
GND on BOTTOM: 36.6,45.24 36.6,53.92 35.26,53.92 35.14,53.81 35.14,50.37 35.12,50.34 34.98,50.34 34.95,50.37 34.95,55.02 34.42,55.55 29.77,55.55 29.51,55.3 29.51,51.18 28.88,50.55 27.41,50.55 26.62,51.33 26.62,53.14 26.06,53.7 13.92,53.7 13.51,53.29 13.51,47.98 13.67,47.83 14.81,47.83 15.44,47.19 15.44,38.43 15.8,38.07 15.8,38.05 16.21,37.64 32.28,37.64 34.34,39.7 34.34,44.68 34.77,45.11 36.47,45.11
GND on BOTTOM: 1.37,12.01 0.56,11.2 0.56,0.86 1.19,0.23 26.09,0.23 26.31,0.46 26.31,3.3 25.63,3.99 19.84,3.99 17.88,5.94 15.27,5.94 14.07,7.14 14.07,9.53 11.58,12.01
GND on INNER1: 26.06,0.23 26.29,0.46 26.29,3.3 25.6,3.99 17.81,3.99 15.82,5.97 15.21,5.97 14.02,7.16 14.02,9.19 14.86,10.03 14.88,10.01 26.34,10.01 26.37,10.03 26.37,12.01 26.34,12.04 6.35,12.04 6.3,11.99 6.25,12.04 0.91,12.04 0.53,11.66 0.53,0.89 1.19,0.23
GND on INNER1: 36.6,47.98 36.58,47.98 36.6,47.96 36.6,45.24 36.47,45.11 34.77,45.11 34.34,44.68 34.34,39.7 29.59,34.95 29.54,34.95 29.16,34.57 22.56,34.57 18.44,30.45 18.44,29.67 17.96,29.18 12.17,29.18 6.98,34.37 6.98,45.29 7.47,45.77 14.99,45.77 15.42,46.2 15.42,47.24 14.78,47.88 5.59,47.88 5.36,48.11 5.36,52.98 5.21,53.14 4.88,53.14 4.7,52.96 4.7,48.03 4.56,47.89 0.85,47.89 0.56,48.18 0.56,55.3 0.81,55.55 36.12,55.55 36.6,55.07 36.6,54.15 36.37,53.92 35.23,53.92 34.98,53.67 34.98,52.73 35.18,52.53 36.37,52.53 36.6,52.3
GND on INNER2: 26.04,0.23 26.26,0.46 26.26,3.3 25.58,3.99 17.78,3.99 15.8,5.97 15.19,5.97 14,7.16 14,9.19 14.83,10.03 14.86,10.01 26.34,10.01 26.37,10.03 26.37,12.01 26.34,12.04 0.89,12.04 0.53,11.68 0.53,0.89 1.19,0.23
GND on INNER2: 36.63,47.96 36.6,47.96 36.63,47.93 36.63,45.24 36.5,45.11 34.8,45.11 34.34,44.65 34.34,39.7 29.21,34.57 22.56,34.57 18.44,30.45 18.44,29.67 17.96,29.18 12.17,29.18 6.98,34.37 6.98,45.29 7.47,45.77 14.99,45.77 15.42,46.2 15.42,47.24 14.81,47.85 5.59,47.85 5.36,48.08 5.36,52.98 5.21,53.14 4.88,53.14 4.7,52.96 4.7,48.03 4.52,47.85 0.89,47.85 0.56,48.18 0.56,55.3 0.81,55.55 5.28,55.55 5.31,55.52 36.14,55.52 36.63,55.04 36.63,54.13 36.4,53.9 35.26,53.9 35,53.64 35,52.71 35.2,52.5 36.4,52.5 36.63,52.27
GND SIGNAL on TOP: 47.73,44.53 47.73,43.38 48.95,42.16 61.9,42.16 65.48,38.58 69.55,38.58 69.98,39.01 69.98,40.16 66.95,43.18 50.83,43.18 49.48,44.53
GND SIGNAL on TOP: 74.84,33.41 74.17,34.09 74.17,43.05 68.53,48.69 66.01,48.69 59.77,54.94 51.74,54.94 51.13,54.33 49.99,54.33 49.99,55.4 50.19,55.6 85.47,55.6 85.8,55.27 85.8,44.15 86.49,43.46 86.49,34.14 85.76,33.41
GND SIGNAL on BOTTOM: 74.88,33.4 79.65,33.4 79.86,33.6 79.86,34.75 71.37,43.23 52.12,43.23 52.12,43.26 51.79,43.59 50.42,43.59 49.48,44.53 47.75,44.53 47.73,44.5 47.73,43.38 48.97,42.14 61.9,42.14 65.51,38.53 69.75,38.53
GND SIGNAL on BOTTOM: 71.12,51.59 84.4,38.3 86.26,38.3 86.51,38.56 86.51,43.48 85.83,44.17 85.83,55.27 85.47,55.63 50.16,55.63 49.91,55.37 49.91,53.09 50.14,52.86 59.36,52.86 60.63,51.59
GND SIGNAL on INNER1: 50.12,55.61 85.48,55.61 85.81,55.27 85.81,44.15 86.5,43.46 86.5,34.14 85.76,33.41 74.94,33.41 74.24,34.1 74.24,35.95 74.15,35.95 71.46,38.64 65.62,38.64 62.85,41.41 49.87,41.41 47.79,43.49 47.79,44.56 49.45,44.56 50.83,43.18 64.95,43.18 67.44,45.67 68.22,45.67 69.21,46.66 69.21,47.98 68.48,48.72 65.33,48.72 60.99,53.06 49.91,53.06 49.91,55.4
GND SIGNAL on INNER2: 50.09,55.61 85.46,55.61 85.79,55.27 85.79,44.15 86.47,43.46 86.47,34.14 85.74,33.41 74.92,33.41 74.22,34.1 74.22,35.95 74.13,35.95 71.44,38.64 65.6,38.64 62.85,41.39 49.87,41.39 47.76,43.49 47.76,44.56 49.52,44.56 50.84,43.23 65.05,43.23 67.49,45.67 68.22,45.67 69.21,46.66 69.21,47.98 68.5,48.69 65.35,48.69 60.91,53.14 60.86,53.14 60.78,53.06 49.91,53.06 49.91,55.43
VO on TOP: 87.45,32.39 91.06,32.39 91.52,31.93 91.52,0.76 90.93,0.18 67.89,0.18 67.41,0.66 67.41,6.65 67.59,6.83 73.51,6.83 73.89,6.45 89.03,6.45 89.61,7.04 89.61,11.2 88.37,12.45 88.37,30.23 87.12,31.47 87.12,32.05
VO on TOP: 55.07,51.13 57.58,51.13 59.79,48.92 59.79,47.7 59.74,47.65 56.39,47.65 56.34,47.7 56.34,49.1 55.7,49.73 55.07,49.73
VO on BOTTOM: 91.49,0.74 90.93,0.18 67.89,0.18 67.41,0.66 67.41,6.65 67.59,6.83 71.58,6.83 74.75,3.66 81.56,3.66 83.79,3.66 84.02,3.89 84.02,6.12 84.25,6.35 89.03,6.35 89.59,6.91 89.59,11.07 88.32,12.34 88.32,30.12 87.1,31.34 87.1,31.9 87.11,31.92 87.11,32.58 87.15,32.61 91.08,32.61 91.49,32.21
VO on INNER1: 87.4,32.39 91.01,32.39 91.47,31.93 91.47,0.86 90.91,0.3 67.77,0.3 67.41,0.66 67.41,5.93 67.97,6.49 73.85,6.49 73.89,6.45 88.98,6.45 89.56,7.04 89.56,11.2 88.32,12.45 88.32,30.23 87.07,31.47 87.07,32.05
VO on INNER2: 87.4,32.39 91.01,32.39 91.47,31.93 91.47,0.86 90.91,0.3 67.72,0.3 67.56,0.46 67.56,6.07 67.94,6.45 88.98,6.45 89.56,7.04 89.56,11.2 88.32,12.45 88.32,30.23 87.07,31.47 87.07,32.05
N37213 on TOP: 22.28,19.66 22.28,19.61 22.25,19.58 5.18,19.58 5.05,19.71 5.05,22.91 4.93,23.04 4.75,23.04 4.62,22.91 4.62,19.74 4.5,19.61 1.6,19.61 1.59,19.62 0.52,19.62 0.2,19.94 0.2,26.14 0.84,26.77 5.79,26.77 7.26,25.3 20.57,25.3 20.57,23.67 22.14,22.11 26.45,22.11 26.47,22.1 26.47,19.71 26.42,19.66
N37213 on BOTTOM: 26.47,22.07 21.74,22.07 21.74,19.66 26.44,19.66 26.47,19.68
N37213 on INNER1, INNER2: 26.31,22.07 26.47,21.92 26.47,19.71 26.42,19.66 5.16,19.66 5.03,19.79 5.03,22.99 4.9,23.11 4.72,23.11 4.6,22.99 4.6,19.81 4.47,19.68 1.57,19.68 1.56,19.7 0.5,19.7 0.18,20.02 0.18,26.21 0.81,26.85 4.39,26.85 9.17,22.07
N37461 on BOTTOM: 83.11,6.32 83.11,4.65 74.8,4.65 72.77,6.68 72.77,7.95 74.17,7.95 74.47,7.65 76.1,7.65 76.1,7.11 76.89,6.32
N37469 on TOP (solid shape): 82.96,13.28 82.04,13.28 82.04,16.2 82.96,16.2
N37469 on TOP (solid shape): 82.98,18.8 82.07,18.8 82.07,21.72 82.98,21.72
N37469 on TOP: 85.7,32.69 86.51,31.88 86.51,30.58 87.35,29.74 87.35,12.09 88.52,10.92 88.52,7.26 88.34,7.09 79.73,7.09 79.5,7.32 79.5,12.04 79.68,12.22 81.53,12.22 82.07,12.75 82.07,16.21 83.44,16.21 83.72,16.48 83.72,18.54 83.52,18.75 82.17,18.75 82.12,18.8 82.12,21.72 83.54,21.72 83.72,21.89 83.72,23.14 83.41,23.44 82.58,23.44 80.19,25.83 80.19,32.18 80.7,32.69
N37469 on TOP: 47.75,45.26 50.29,45.26 50.39,45.36 55.37,45.36 55.42,45.31 65.43,45.31 65.93,44.82 65.91,44.81 65.91,44.07 65.53,43.69 50.8,43.69 49.66,44.83 47.75,44.83
N37469 on BOTTOM: 80.92,35.13 72.31,43.74 52.58,43.74 52.04,44.27 50.27,44.27 49.83,44.7 49.83,45.64 49.99,45.8 72.77,45.8 86.46,32.11 86.46,30.78 87.3,29.95 87.3,12.32 88.47,11.15 88.47,8.05 77.04,8.05 76.99,8.1 76.99,8.46 76.02,9.42 74.88,9.42 74.85,9.45 74.85,10.24 79.96,10.24 81.94,12.22 81.94,16.15 82.12,16.33 83.36,16.33 83.57,16.54 83.57,30.4 82.63,31.34 82.63,31.37 80.92,33.07
N37469 on INNER1: 80.17,27.11 80.19,27.13 80.19,32.21 80.67,32.69 85.7,32.69 86.51,31.88 86.51,30.58 87.35,29.74 87.35,12.09 88.52,10.92 88.52,7.26 88.34,7.09 79.73,7.09 79.5,7.32 79.5,12.04 79.68,12.22 81.51,12.22 82.04,12.75 82.04,16.21 83.44,16.21 83.72,16.48 83.72,18.54 83.52,18.75 82.14,18.75 82.09,18.8 82.09,21.69 82.14,21.74 83.54,21.74 83.72,21.92 83.72,23.09 83.36,23.44 82.6,23.44 80.17,25.88
N37469 on INNER1: 49.53,45.26 50.29,45.26 53.98,48.95 61.95,48.95 64.85,46.05 64.85,43.94 64.59,43.69 50.88,43.69 49.53,45.03
N37469 on INNER2: 49.53,45.26 49.53,45.03 50.88,43.69 64.59,43.69 64.85,43.94 64.85,46.05 61.95,48.95 53.98,48.95 50.29,45.26
N37469 on INNER2: 80.14,27.11 80.16,27.13 80.16,32.21 80.64,32.69 85.67,32.69 86.49,31.88 86.49,30.58 87.33,29.74 87.33,12.09 88.49,10.92 88.49,7.26 88.32,7.09 79.71,7.09 79.48,7.32 79.48,12.04 79.65,12.22 81.48,12.22 82.07,12.8 82.07,16.18 83.41,16.18 83.69,16.46 83.69,18.54 83.49,18.75 82.14,18.75 82.09,18.8 82.09,21.69 82.14,21.74 83.54,21.74 83.72,21.92 83.72,23.09 83.36,23.44 82.58,23.44 80.14,25.88
N37817 on TOP: 0.76,35.33 3.91,35.33 4.04,35.2 4.04,29.39 3.96,29.31 0.71,29.31 0.66,29.36 0.66,35.23
N38055 on TOP: 18.54,5.38 17.5,5.38 17.3,5.59 17.3,6.83 16.94,7.19 15.29,7.19 14.81,7.67 14.81,8.84 15.27,9.3 18.52,9.3 18.54,9.27
N38055 on TOP: 27.64,52.91 27.28,52.55 27.28,51.64 27.61,51.31 30.12,51.31 30.25,51.44 30.25,52.76 30.1,52.91
N51802 on TOP: 87.27,34.37 90.73,34.37 91.21,34.85 91.21,55.4 91.03,55.58 86.89,55.58 86.72,55.4 86.72,46.02 87.86,44.88 87.86,36.91 87.01,36.06 87.01,34.63
N51802 on BOTTOM: 88.65,33.88 87.02,35.51 87.02,36.09 87.86,36.93 87.86,44.91 86.72,46.05 86.72,55.4 86.89,55.58 91.06,55.58 91.36,55.27 91.36,34.21 91.03,33.88
N51802 on INNER1: 87.52,34.37 90.73,34.37 91.21,34.85 91.21,55.4 91.03,55.58 86.89,55.58 86.72,55.4 86.72,46.02 87.86,44.88 87.86,36.91 87.21,36.26 87.21,34.67
N51802 on INNER2: 87.27,34.39 90.73,34.39 91.21,34.87 91.21,55.42 91.03,55.6 86.89,55.6 86.72,55.42 86.72,46.02 87.86,44.88 87.86,36.93 87.01,36.08 87.01,34.66
N100534 on TOP: 18.06,31.14 13.82,31.14 13.69,31.01 13.69,27.25 13.92,27.03 20.57,27.03 20.62,27.08 20.62,28.57
N100538 on TOP: 13.94,34.49 21.59,34.49 21.62,34.52 21.64,34.49 21.64,32.18 21.62,32.16 18.77,32.16 18.11,32.82 13.94,32.82
N104424 on TOP (solid shape): 81.05,12.86 76.5,12.86 76.5,17.86 81.05,17.86
N104424 on TOP (solid shape): 81.08,18.37 76.53,18.37 76.53,23.37 81.08,23.37
N104424 on TOP: 72.24,31.42 71.86,31.8 71.86,37.85 71.7,38 71.27,38 70.97,37.69 67.69,37.69 67.49,37.49 67.49,7.98 68.05,7.42 78.36,7.42 78.72,7.78 78.72,9.29 78.71,9.3 78.71,12.65 78.92,12.85 81.05,12.85 81.08,12.88 81.08,23.8 79.25,25.63 79.25,30.89 78.71,31.42
N104424 on BOTTOM: 81.18,23.44 81.18,12.75 79.43,11 74.6,11 74.02,10.41 74.02,8.84 72.29,8.84 72.11,8.66 72.11,7.59 71.93,7.42 68.05,7.42 67.49,7.98 67.49,37.64 67.61,37.77 69.8,37.77 71.88,35.69 71.88,31.85 72.31,31.42 78.74,31.42 79.58,30.58 79.58,28.8 78.6,27.83 78.6,24.09 79.1,23.6 81.03,23.6
N104424 on INNER1: 71.83,31.88 71.83,35.56 69.75,37.64 67.56,37.64 67.48,37.55 67.48,29.48 67.49,29.46 67.49,8.03 67.92,7.59 78.41,7.59 78.69,7.88 78.69,9.27 78.7,9.27 78.7,12.64 78.93,12.87 78.94,12.85 81.05,12.85 81.08,12.88 81.08,23.72 79.3,25.5 79.27,25.5 79.02,25.76 79.02,26.52 79.04,26.54 79.04,30.76 78.59,31.22 72.49,31.22
N104424 on INNER2: 71.83,31.88 71.83,35.56 69.75,37.64 67.56,37.64 67.48,37.55 67.48,29.48 67.49,29.46 67.49,8.05 67.94,7.59 78.41,7.59 78.69,7.88 78.69,9.27 78.7,9.27 78.7,12.64 78.92,12.85 81.13,12.85 81.08,12.9 81.08,23.72 79.3,25.5 79.27,25.5 79.02,25.76 79.02,26.52 79.04,26.54 79.04,30.76 78.59,31.22 72.49,31.22
N108749 on TOP: 55.55,48.9 55.45,49 53.67,49 52.22,47.55 52.22,46.28 52.35,46.15 53.9,46.15 54.1,45.95 56.59,45.95 56.85,45.69 58.12,45.69 58.14,45.72 58.14,47.12 55.93,47.12 55.55,47.5
N109833 on TOP: 61.9,48.9 61.9,47.04 60.55,45.69 59,45.69 59,46.99 60.25,46.99 60.66,47.4 60.66,48.9
N12285951 on BOTTOM: 81.48,29.11 81.51,29.08 82.5,29.08 82.55,29.13 82.55,30.35 82.35,30.56 81.58,30.56 81.48,30.45
N12285951 on BOTTOM: 83.16,17.14 82.98,16.97 82.12,16.97 81.94,17.14 81.94,25.68 81.58,26.04 81.58,27.3 81.61,27.33 82.83,27.33 83.16,27
N12285992 on BOTTOM: 80.7,24.18 80.49,23.98 79.32,23.98 79.26,24.04 79.26,27.5 79.45,27.69 79.48,27.69 80.37,28.57 80.37,29.08 80.92,29.08 81.56,28.45 82.47,28.45 82.5,28.42 82.5,27.84 82.46,27.8 81.04,27.8 80.7,27.46
N12290249 on TOP: 26.52,7.04 20.27,7.04 20.19,6.96 20.19,5.03 20.29,4.93 26.52,4.93 26.59,5 26.59,6.96
N12290249 on BOTTOM: 20.27,7.04 20.19,6.96 20.19,5.03 20.29,4.93 26.52,4.93 26.59,5 26.59,6.96 26.52,7.04
N12293127 on TOP: 47.88,48.59 49.99,48.59 50.98,49.58 50.98,51.33 51.61,51.97 53.44,51.97 53.47,51.99 53.47,53.57 53.26,53.77 50.01,53.77 49.83,53.59 49.83,49.17 49.68,49.02 47.88,49.02 47.83,48.97 47.83,48.64
N12298344 on TOP: 36.6,38.51 26.7,28.6 26.7,25.2 26.47,24.97 23.49,24.97 23.39,25.07 23.39,34.54 30.02,34.54 34.85,39.37 34.85,44.53 36.6,44.53
N12298344 on BOTTOM: 23.49,24.97 26.47,24.97 26.7,25.2 26.7,34.44 26.49,34.65 23.49,34.65 23.39,34.54 23.39,25.07
N12333480 on TOP: 0.84,43.23 3.91,43.23 3.91,37.9 3.84,37.82 0.84,37.82 0.74,37.92 0.74,43.13

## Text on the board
Ref Des/Silkscreen Bottom: S/N | 2205 | REV D | DER-913
Ref Des/Silkscreen Top: TM | InnoSwitch | 3-EP
User.5: 14.  FAB HOUSE LOGO,DATE CODE TO BE IN SILK SCREEN ONLY.DO NOT USE COPPER. | 13.  MATERIAL FR4 COPPER 2oz THICKNESS 0.062" | PLEASE DELETE THESE PINS
User.8: FIGURE | FINISHED_SIZE | 18.0 | 20.0 | 35.0 | 67.0 | 68.0 | DRILL CHART: TOP to BOTTOM | ALL UNITS ARE IN MILS | TOLERANCE_DRILL | +3.0/-3.0 | +0.0/-0.0 | PLATED | QTY | 1195 | 3 | 4 | 2
